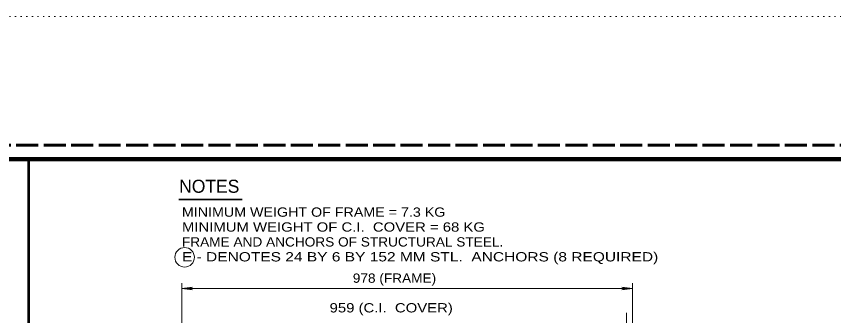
# Model space of a CAD drawing. Extents: x 312583 to 312854, y 144419 to 144597.
# Drawn here: x 312674.5 to 312741.4, y 144572.3 to 144596.8 of the extents above; entities that cross this region are included whole.
import ezdxf
from ezdxf.enums import TextEntityAlignment as Align

# ---------------------------------------------------------------- set-up
doc = ezdxf.new("R2010")
doc.units = 0
doc.header["$LTSCALE"] = 0.3
doc.linetypes.add('DOTTED', pattern=[1.5, 0.3, -1.2])
doc.linetypes.add('LONG_DASHED', pattern=[7.5, 6, -1.5])
for name, color, linetype, lineweight in [('1', 7, 'Continuous', 40), ('2', 7, 'Continuous', 13), ('63', 7, 'DOTTED', 13)]:
    doc.layers.add(name, color=color, linetype=linetype, lineweight=lineweight)

msp = doc.modelspace()

# ---------------------------------------------------------------- linework, layer by layer
at = {"layer": '1', "linetype": 'LONG_DASHED', "lineweight": 60}
msp.add_line((312851.75, 144586.2246), (312583.526, 144586.2246), dxfattribs=at)
at = {"layer": '1', "lineweight": 53}
msp.add_line((312675.4374, 144585.0846), (312675.4374, 144521.3091), dxfattribs=at)
at = {"layer": '1', "lineweight": 35}
msp.add_line((312687.779, 144581.7805), (312692.966, 144581.7805), dxfattribs=at)
at = {"layer": '1', "lineweight": 158}
msp.add_lwpolyline([(312616.5, 144423.1446), (312616.5, 144585.0846), (312849, 144585.0846)], dxfattribs=at)
at = {"layer": '2'}
for p, q in [((312688.0165, 144562.8636), (312688.0165, 144574.9386)), ((312688.0165, 144574.5016), (312688.8829, 144574.6089)), ((312688.8829, 144574.6089), (312688.6069, 144574.5016)), ((312724.0729, 144574.6089), (312724.3489, 144574.5016)), ((312724.9392, 144574.5016), (312724.0729, 144574.6089)), ((312724.9392, 144562.7639), (312724.9392, 144574.9386)), ((312688.0165, 144574.5016), (312724.9392, 144574.5016)), ((312688.0165, 144574.5016), (312688.8829, 144574.3943)), ((312688.8829, 144574.3943), (312688.6069, 144574.5016)), ((312724.0729, 144574.3943), (312724.3489, 144574.5016)), ((312724.9392, 144574.5016), (312724.0729, 144574.3943)), ((312724.4715, 144562.7946), (312724.4715, 144572.5083))]:
    msp.add_line(p, q, dxfattribs=at)
msp.add_circle((312688.2466, 144577.0505), 0.8012, dxfattribs=at)
at = {"layer": '63'}
msp.add_line((312601.2, 144596.7846), (312853.5, 144596.7846), dxfattribs=at)

# ---------------------------------------------------------------- texts
at = {"layer": '2'}
msp.add_text('NOTES', height=1.07, dxfattribs=at).set_placement((312690.2635, 144582.3347), align=Align.CENTER)
for s, width, p in [('MINIMUM WEIGHT OF FRAME = 7.3 KG', 1.15, (312688.0244, 144580.3731)), ('MINIMUM WEIGHT OF C.I.  COVER = 68 KG', 1.2, (312688.0244, 144579.1531)), ('FRAME AND ANCHORS OF STRUCTURAL STEEL.', 1.1, (312688.0244, 144577.9331)), ('E - DENOTES 24 BY 6 BY 152 MM STL.  ANCHORS (8 REQUIRED)', 1.25, (312688.0244, 144576.7131)), ('978 (FRAME)', 1.1, (312702.0269, 144574.9664)), ('959 (C.I.  COVER)', 1.2, (312700.1262, 144572.5361))]:
    msp.add_text(s, height=0.76, dxfattribs=dict(at, width=width)).set_placement(p)

doc.saveas('drawing.dxf')
